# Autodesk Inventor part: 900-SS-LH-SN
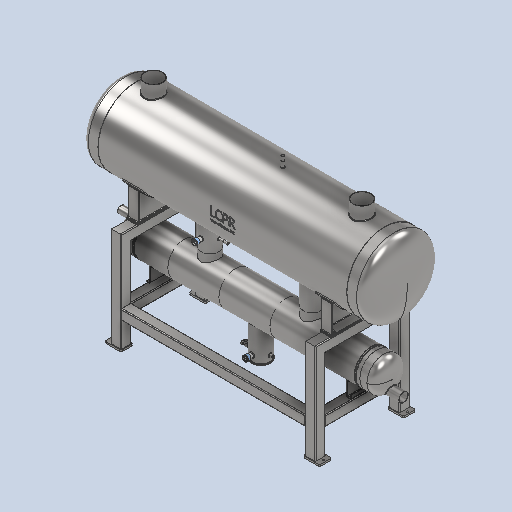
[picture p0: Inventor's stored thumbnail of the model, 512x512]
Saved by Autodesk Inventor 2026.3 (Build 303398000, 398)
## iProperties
Created: 2026-05
Part Number: 900-SS-LH-SN
Material: Generic
Document SubType Name: Modeling
Designer: rva
Density: 1 g/cm^3
Appearance: Default
Author: rva
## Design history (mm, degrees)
derived "LCPR-SS-900-LH-SN.iam"
body "Solid1"
node "Sub-SS-400-200-2646-200-100-75-LH.iam:1::LCPR-SS-400 mm Subc"
node "Sub-SS-400-200-2646-200-100-75-LH.iam:1::LCPR-SS-400 mm Subc"
node "Sub-SS-400-200-2646-200-100-75-LH.iam:1::H1100-R.ipt:2"
node "Sub-SS-400-200-2646-200-100-75-LH.iam:1::1-2 Inch NPT Socket"
node "Sub-SS-400-200-2646-200-100-75-LH.iam:1::Welds"
node "Sub-SS-400-200-2646-200-100-75-LH.iam:1::200 mm Oil Pot Asse"
node "LPR-900-Frame Assembly.iam:1::LCPR-SS-Frame FOOT PLATE 195 x"
node "LPR-900-Frame Assembly.iam:1::LCPR-SS-Frame FOOT PLATE 195 x"
node "LPR-900-Frame Assembly.iam:1::LCPR-SS-Frame FOOT PLATE 195 x"
node "LPR-900-Frame Assembly.iam:1::LCPR-SS-Frame FOOT PLATE 195 x"
node "Nylon Heat Tranfer Spacer 760x125.ipt:1"
node "Nylon Heat Tranfer Spacer 760x125.ipt:2"
node "AS 1111 - Metric M16 x 160:1"
node "AS 1112 (4) - Metric M16:1"
node "AS 1237 (4.2) 16 mm:1"
node "AS 1237 (4.2) 16 mm:2"
node "AS 1111 - Metric M16 x 160:2"
node "AS 1112 (4) - Metric M16:2"
node "AS 1237 (4.2) 16 mm:3"
node "AS 1237 (4.2) 16 mm:4"
node "AS 1111 - Metric M16 x 160:3"
node "AS 1112 (4) - Metric M16:3"
node "AS 1237 (4.2) 16 mm:5"
node "AS 1237 (4.2) 16 mm:6"
node "AS 1111 - Metric M16 x 160:4"
node "AS 1112 (4) - Metric M16:4"
node "AS 1237 (4.2) 16 mm:7"
node "AS 1237 (4.2) 16 mm:8"
node "LCPR-SS-900-3000-200-SN-WELD.iam:1::900 mm LOGO.iam:1::LCPR-"
node "LCPR-SS-900-3000-200-SN-WELD.iam:1::H1100-R.ipt:1"
node "LCPR-SS-900-3000-200-SN-WELD.iam:1::LCPR-SS-900-Leg Assembly"
node "LCPR-SS-900-3000-200-SN-WELD.iam:1::900 mm-SS-Dome End Cap.i"
node "LCPR-SS-900-3000-200-SN-WELD.iam:1::LCPR-SS-900-Leg Assembly"
node "LCPR-SS-900-3000-200-SN-WELD.iam:1::900 mm-SS-Dome End Cap.i"
node "LCPR-SS-900-3000-200-SN-WELD.iam:1::Welds"
node "LCPR-SS-900-LH-SN.iam_Bodies"
